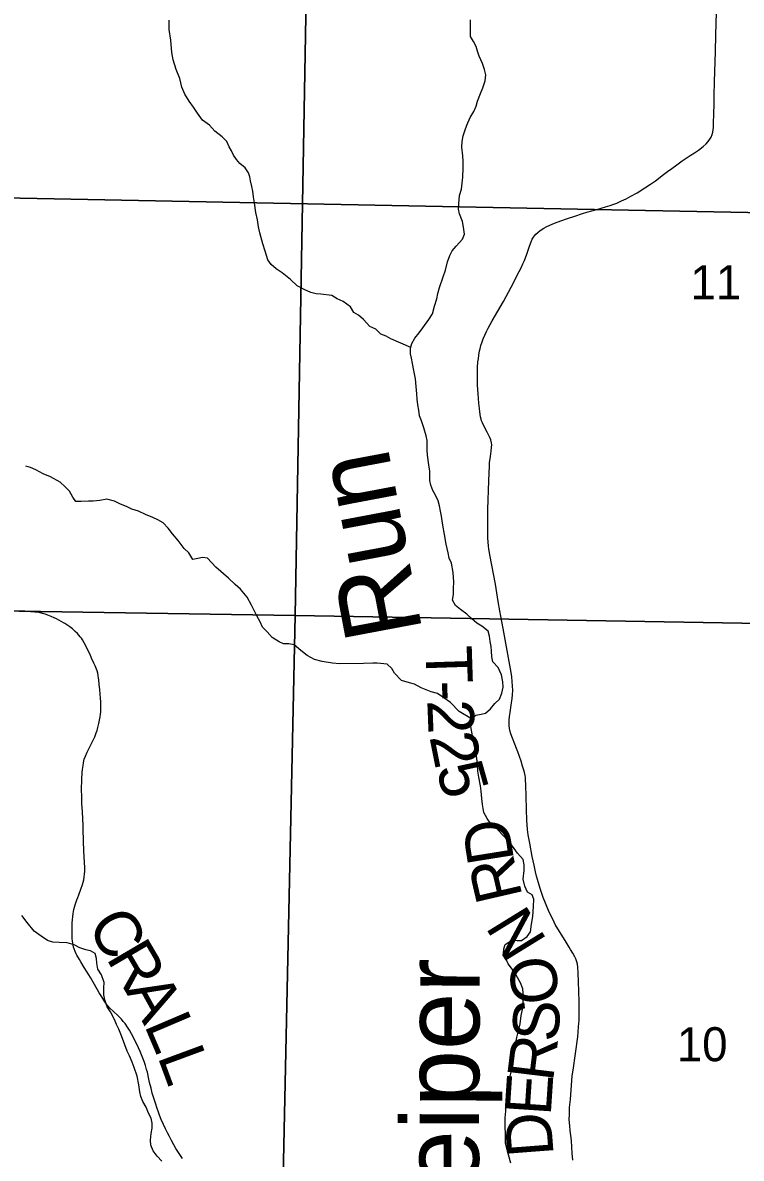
# Model space of a CAD drawing. Extents: x 0 to 34, y 0 to 22.
# Drawn here: x 21.94 to 22.822, y 17.999 to 19.394 of the extents above; entities that cross this region are included whole.
import ezdxf

# ---------------------------------------------------------------- set-up
doc = ezdxf.new("R2010")
doc.units = 0
for name, color, linetype in [('GM_X_Corporation', 7, 'Continuous'), ('GM_X_Minor_River', 7, 'Continuous'), ('GM_X_Minor_River_Text', 7, 'Continuous'), ('GM_X_Section_Text', 7, 'Continuous'), ('GM_X_Township_Road', 7, 'Continuous'), ('GM_X_Township_Road_Text', 7, 'Continuous')]:
    doc.layers.add(name, color=color, linetype=linetype)

msp = doc.modelspace()

# ---------------------------------------------------------------- linework, layer by layer
at = {"layer": 'GM_X_Corporation'}
for points in [[(25.4, 19.0068), (25.4, 20.4), (21.2921, 20.4), (21.2757, 19.6748), (21.2742, 19.6071), (21.273, 19.5535), (21.2652, 19.1913), (21.5297, 19.1865), (21.7744, 19.1817), (21.8956, 19.1793), (22.6423, 19.1645), (23.3329, 19.1508), (23.5499, 19.1465), (23.786, 19.1434), (24.169, 19.1418), (24.3186, 19.1409), (24.3186, 19.0261), (24.5766, 19.0222)], [(22.2928, 19.6778), (22.2749, 18.6656), (21.2582, 18.6819), (21.2769, 19.6922)], [(22.2928, 19.6778), (23.3052, 19.6529), (23.3004, 18.648), (22.2749, 18.6656)], [(21.2582, 18.6819), (22.2749, 18.6656), (22.2529, 17.6514), (21.2422, 17.6682)], [(22.2749, 18.6656), (23.3004, 18.648), (23.2763, 17.6399), (22.2529, 17.6514)]]:
    msp.add_lwpolyline(points, close=True, dxfattribs=at)
msp.add_lwpolyline([(25.4, 14.4307), (25.4, 19.0068), (24.5766, 19.0222), (24.3186, 19.0261), (24.3186, 19.1409), (24.169, 19.1418), (23.786, 19.1434), (23.5499, 19.1465), (23.3329, 19.1508), (22.6423, 19.1645), (21.8956, 19.1793), (21.7744, 19.1817), (21.5297, 19.1865), (21.2652, 19.1913), (20.8916, 19.1966), (20.254, 19.2058), (20.2471, 18.8539), (20.2208, 16.9558), (20.1987, 15.2691)], dxfattribs=at)
at = {"layer": 'GM_X_Minor_River'}
for points in [[(22.4167, 18.995), (22.3921, 19.0057), (22.3864, 19.0087), (22.3799, 19.0112), (22.3737, 19.0176), (22.3665, 19.0209), (22.3588, 19.0292), (22.3523, 19.0348), (22.3469, 19.0381), (22.3427, 19.0449), (22.3335, 19.0516), (22.3262, 19.0549), (22.3197, 19.059), (22.3061, 19.0603), (22.3004, 19.061), (22.2939, 19.0624), (22.2859, 19.0661), (22.2772, 19.0709), (22.2691, 19.0784), (22.2588, 19.0866), (22.2515, 19.0915), (22.2454, 19.0971), (22.2411, 19.1027), (22.2379, 19.1133), (22.2351, 19.1224), (22.2315, 19.1357), (22.2299, 19.1433), (22.2287, 19.1516), (22.2266, 19.1607), (22.2249, 19.1725), (22.2237, 19.1801), (22.2228, 19.1869), (22.2216, 19.1926), (22.22, 19.1995), (22.2192, 19.2044), (22.2176, 19.2097), (22.2133, 19.2157), (22.2068, 19.221), (22.2026, 19.2258), (22.1991, 19.2311), (22.1964, 19.2364), (22.1936, 19.2413), (22.1909, 19.2481), (22.1851, 19.2537), (22.1763, 19.2608), (22.1694, 19.268), (22.161, 19.2743), (22.1548, 19.283), (22.1498, 19.2901), (22.1447, 19.2976), (22.1393, 19.3063), (22.1358, 19.3146), (22.133, 19.3252), (22.1286, 19.3366), (22.1251, 19.3483), (22.1234, 19.3574), (22.1221, 19.3723), (22.12, 19.3856), (22.1199, 19.3913), (22.1202, 19.397)], [(22.4812, 19.2548), (22.483, 19.2613), (22.4855, 19.2682), (22.4896, 19.2774), (22.494, 19.2847), (22.497, 19.2912), (22.4984, 19.2974), (22.5024, 19.3069), (22.505, 19.3138), (22.5079, 19.3226), (22.5089, 19.3299), (22.5073, 19.3363), (22.5049, 19.3439), (22.5006, 19.353), (22.4986, 19.359), (22.497, 19.3647), (22.4935, 19.3707), (22.49, 19.3771), (22.4898, 19.3897), (22.4901, 19.3973)], [(22.4919, 18.5205), (22.4907, 18.5269), (22.4899, 18.5326), (22.4905, 18.5383), (22.4965, 18.5434), (22.5029, 18.5446), (22.5086, 18.5459), (22.5146, 18.5513), (22.5198, 18.5578), (22.5254, 18.5632), (22.5283, 18.5705), (22.5301, 18.5778), (22.5296, 18.5842), (22.528, 18.593), (22.5241, 18.602), (22.5175, 18.6088), (22.5163, 18.6149), (22.5158, 18.6221), (22.5154, 18.6278), (22.5141, 18.6339), (22.5133, 18.6403), (22.5117, 18.6464), (22.504, 18.6527), (22.4979, 18.6564), (22.4914, 18.662), (22.4856, 18.6673), (22.4776, 18.6733), (22.4715, 18.6781), (22.468, 18.6845), (22.469, 18.6918), (22.4693, 18.6994), (22.4695, 18.7066), (22.4686, 18.7188), (22.4665, 18.7302), (22.4638, 18.7362), (22.4626, 18.7427), (22.4601, 18.7533), (22.4581, 18.7654), (22.456, 18.7768), (22.4543, 18.7878), (22.4531, 18.7939), (22.4519, 18.8004), (22.4503, 18.8068), (22.4471, 18.8136), (22.4436, 18.8193), (22.4413, 18.8257), (22.4401, 18.8318), (22.44, 18.8375), (22.4399, 18.8432), (22.439, 18.8508), (22.4373, 18.8629), (22.4369, 18.869), (22.4367, 18.8808), (22.4355, 18.8865), (22.4327, 18.8963), (22.4299, 18.9051), (22.4275, 18.9111), (22.4267, 18.918), (22.4255, 18.9244), (22.4246, 18.9316), (22.4241, 18.9381), (22.4232, 18.9472), (22.4223, 18.9563), (22.4203, 18.9666), (22.419, 18.9753), (22.4174, 18.9817), (22.4162, 18.9874), (22.4165, 18.9943), (22.4179, 19), (22.4216, 19.0066), (22.4268, 19.0131), (22.4316, 19.0193), (22.4387, 19.0293), (22.4435, 19.0362), (22.446, 19.0457), (22.4485, 19.0549), (22.45, 19.0614), (22.4521, 19.0687), (22.4565, 19.0817), (22.4594, 19.0901), (22.4619, 19.1), (22.4648, 19.1081), (22.4674, 19.1138), (22.4726, 19.1196), (22.48, 19.1281), (22.4826, 19.1342), (22.4813, 19.1426), (22.4801, 19.1498), (22.4765, 19.1592), (22.4753, 19.1649), (22.4756, 19.1714), (22.4766, 19.1817), (22.4788, 19.1893), (22.4798, 19.197), (22.4804, 19.2042), (22.481, 19.2153), (22.4809, 19.2236), (22.4804, 19.2305), (22.4795, 19.2411), (22.4798, 19.248), (22.4812, 19.2548)], [(22.4913, 18.539), (22.476, 18.548), (22.4656, 18.5589), (22.4561, 18.5656), (22.4496, 18.5701), (22.4416, 18.5722), (22.4355, 18.5744), (22.4294, 18.577), (22.4214, 18.5814), (22.4153, 18.5832), (22.4054, 18.5858), (22.3966, 18.5951), (22.3935, 18.6008), (22.3877, 18.606), (22.3756, 18.6074), (22.3703, 18.6073), (22.3585, 18.6067), (22.329, 18.6063), (22.3207, 18.6073), (22.3078, 18.6094), (22.2983, 18.6119), (22.2895, 18.6167), (22.2818, 18.6227), (22.2734, 18.6298), (22.2669, 18.6308), (22.2605, 18.6311), (22.2552, 18.6333), (22.2464, 18.6389), (22.2402, 18.6456), (22.2348, 18.6516), (22.2317, 18.6581), (22.2278, 18.6652), (22.2247, 18.6713), (22.2212, 18.6785), (22.2157, 18.6883), (22.2076, 18.698), (22.2011, 18.704), (22.1931, 18.7115), (22.1773, 18.725), (22.167, 18.7362), (22.1609, 18.7369), (22.1552, 18.7357), (22.1492, 18.7344), (22.1441, 18.7427), (22.1384, 18.748), (22.131, 18.7581), (22.1241, 18.766), (22.1187, 18.7732), (22.1129, 18.7796), (22.1061, 18.7833), (22.1, 18.7862), (22.0912, 18.7899), (22.0824, 18.7939), (22.0744, 18.7965), (22.0687, 18.7994), (22.0596, 18.8031), (22.0531, 18.8064), (22.0436, 18.8086), (22.0349, 18.8069), (22.0266, 18.8064), (22.0209, 18.8063), (22.0122, 18.8058), (22.0054, 18.8057), (22.0019, 18.8113), (21.9976, 18.8185), (21.9926, 18.8238), (21.9861, 18.8297), (21.9743, 18.836), (21.9655, 18.8397), (21.9564, 18.8449), (21.9499, 18.8475), (21.9442, 18.8493)], [(22.5394, 17.993), (22.5366, 18.0032), (22.5346, 18.0112), (22.533, 18.018), (22.5325, 18.0488), (22.5332, 18.0572), (22.5338, 18.064), (22.5341, 18.0736), (22.5351, 18.0797), (22.5357, 18.0888), (22.5389, 18.1018), (22.5411, 18.1098), (22.5421, 18.1163), (22.5432, 18.1224), (22.5435, 18.1289), (22.5452, 18.1392), (22.547, 18.1476), (22.5495, 18.1575), (22.5509, 18.1644), (22.5523, 18.1743), (22.5537, 18.1819), (22.5547, 18.1907), (22.555, 18.1972), (22.5544, 18.2071), (22.5513, 18.2146), (22.5462, 18.2241), (22.5416, 18.2309), (22.5362, 18.238), (22.5334, 18.2444), (22.5307, 18.2501), (22.531, 18.2562), (22.5324, 18.2619), (22.5414, 18.2674), (22.5471, 18.2667), (22.5528, 18.2668), (22.5596, 18.2715), (22.5636, 18.2772), (22.565, 18.2868), (22.5664, 18.2959), (22.5673, 18.3085), (22.5676, 18.3173), (22.5656, 18.3229), (22.5599, 18.3259), (22.5568, 18.3335), (22.5547, 18.3418), (22.5557, 18.3525), (22.556, 18.3597), (22.5548, 18.3662), (22.5478, 18.3737), (22.5417, 18.3823), (22.5363, 18.3891), (22.5293, 18.3966), (22.5216, 18.4052), (22.5151, 18.4101), (22.5105, 18.4165), (22.5062, 18.424), (22.5049, 18.4335), (22.5041, 18.4411), (22.5032, 18.4502), (22.5023, 18.4567), (22.5003, 18.4673), (22.499, 18.4745), (22.4985, 18.4825), (22.4977, 18.4901), (22.4964, 18.4992), (22.4944, 18.5064), (22.4928, 18.5148), (22.4919, 18.5205)], [(22.1111, 17.9955), (22.1054, 18.0019), (22.1004, 18.0083), (22.0976, 18.0151), (22.0971, 18.0212), (22.0981, 18.0296), (22.0992, 18.0361), (22.0991, 18.0422), (22.0979, 18.0486), (22.0947, 18.0546), (22.092, 18.0618), (22.0877, 18.069), (22.0854, 18.0751), (22.0841, 18.0807), (22.0829, 18.0895), (22.0808, 18.1001), (22.0773, 18.1107), (22.0745, 18.1171), (22.0714, 18.1251), (22.0686, 18.1307), (22.0655, 18.1383), (22.0616, 18.1497), (22.0584, 18.1576), (22.0553, 18.1636), (22.0529, 18.1697), (22.0479, 18.1788), (22.044, 18.1852), (22.0412, 18.1939), (22.04, 18.1999), (22.0399, 18.2083), (22.0402, 18.2152), (22.037, 18.2246), (22.0327, 18.2314), (22.0311, 18.2386), (22.031, 18.2447), (22.0294, 18.2508), (22.0237, 18.2541), (22.0176, 18.2552), (22.0104, 18.2577), (22.0035, 18.2614), (21.9948, 18.2636), (21.9849, 18.2642), (21.9773, 18.2644), (21.9709, 18.2666), (21.9628, 18.2718), (21.9544, 18.2782), (21.9459, 18.2887), (21.939, 18.2973)]]:
    msp.add_lwpolyline(points, dxfattribs=at)
at = {"layer": 'GM_X_Township_Road'}
for points in [[(22.6558, 19.1676), (22.6616, 19.1694), (22.6647, 19.1705), (22.6695, 19.1724), (22.6755, 19.175), (22.6811, 19.1777), (22.687, 19.1809), (22.6945, 19.1849), (22.7042, 19.1911), (22.7108, 19.1956), (22.717, 19.1998), (22.727, 19.2073), (22.732, 19.2111), (22.7372, 19.215), (22.7431, 19.2195), (22.7498, 19.2241), (22.7595, 19.2306), (22.765, 19.2342), (22.7699, 19.2375), (22.7756, 19.2417), (22.7794, 19.2451), (22.7819, 19.2478), (22.784, 19.2508), (22.7853, 19.2532), (22.7865, 19.2564), (22.7873, 19.2595), (22.7878, 19.2623), (22.7882, 19.2652), (22.7884, 19.2693), (22.7888, 19.2833), (22.789, 19.2928), (22.7892, 19.3051), (22.7897, 19.3213), (22.7906, 19.3587), (22.791, 19.3788), (22.7922, 19.4069)], [(22.5123, 18.8877), (22.5105, 18.891), (22.5081, 18.8956), (22.5046, 18.9026), (22.5037, 18.905), (22.5031, 18.9068), (22.5024, 18.9098), (22.5014, 18.916), (22.501, 18.9199), (22.5003, 18.9265), (22.4994, 18.9382), (22.4987, 18.9487), (22.4985, 18.9562), (22.4987, 18.9705), (22.4992, 18.9774), (22.4997, 18.9812), (22.5004, 18.9856), (22.5012, 18.9909), (22.5018, 18.9935), (22.5027, 18.9973), (22.5042, 19.0019), (22.5057, 19.0058), (22.5096, 19.0148), (22.5116, 19.0188), (22.5165, 19.0276), (22.5305, 19.0515), (22.5399, 19.0692), (22.5428, 19.0745), (22.5458, 19.0806), (22.5498, 19.0883), (22.552, 19.0929), (22.5544, 19.0979), (22.5562, 19.102), (22.5592, 19.1095), (22.5604, 19.1132), (22.5622, 19.1184), (22.5636, 19.1227), (22.5645, 19.1249), (22.5659, 19.1279), (22.5672, 19.1305), (22.5684, 19.1322), (22.5702, 19.1342), (22.5726, 19.1364), (22.5757, 19.1387), (22.58, 19.1414), (22.583, 19.1431), (22.5873, 19.1452), (22.5931, 19.1476), (22.6008, 19.1505), (22.609, 19.1534), (22.6179, 19.1564), (22.6274, 19.1594), (22.6327, 19.161), (22.639, 19.1629), (22.6449, 19.1644), (22.6558, 19.1676)], [(22.6156, 17.9969), (22.6149, 18.0056), (22.6144, 18.0129), (22.6138, 18.0208), (22.6125, 18.0331), (22.6118, 18.0391), (22.6113, 18.0469), (22.6115, 18.0531), (22.6116, 18.0616), (22.6126, 18.0715), (22.615, 18.1004), (22.6159, 18.1075), (22.6216, 18.1481), (22.6222, 18.1542), (22.6227, 18.1607), (22.6232, 18.1689), (22.6235, 18.1798), (22.6236, 18.1858), (22.6235, 18.1917), (22.6231, 18.2041), (22.6227, 18.2163), (22.6222, 18.2266), (22.6217, 18.2338), (22.6213, 18.2376), (22.6207, 18.2403), (22.6193, 18.2439), (22.618, 18.2466), (22.6156, 18.2511), (22.6129, 18.2557), (22.6113, 18.2585), (22.6063, 18.2665), (22.5973, 18.281), (22.5941, 18.2864), (22.5913, 18.2921), (22.5887, 18.2974), (22.5859, 18.3036), (22.5794, 18.3196), (22.5756, 18.3304), (22.5735, 18.3373), (22.5711, 18.3455), (22.5698, 18.3508), (22.568, 18.3593), (22.5658, 18.3696), (22.5627, 18.3861), (22.5608, 18.3965), (22.5599, 18.4028), (22.5594, 18.4089), (22.5591, 18.4138), (22.5581, 18.4578), (22.5577, 18.4638), (22.5574, 18.467), (22.557, 18.4694), (22.5562, 18.473), (22.5556, 18.4757), (22.554, 18.4808), (22.5521, 18.4867), (22.5481, 18.4982), (22.5466, 18.5023), (22.5394, 18.5206), (22.5386, 18.5234), (22.5377, 18.5272), (22.5374, 18.5307), (22.5376, 18.5374), (22.538, 18.5419), (22.5386, 18.5465), (22.54, 18.5555), (22.5412, 18.564), (22.5416, 18.5685), (22.5418, 18.574), (22.5417, 18.5789), (22.5412, 18.5846), (22.5406, 18.5903), (22.5398, 18.5958), (22.5301, 18.65), (22.5285, 18.6583), (22.5261, 18.6717), (22.5241, 18.6829), (22.5205, 18.7041), (22.5138, 18.7402), (22.5133, 18.743), (22.5125, 18.7471), (22.5122, 18.7512), (22.5117, 18.7558), (22.5114, 18.7612), (22.5112, 18.7705), (22.5114, 18.7962), (22.5125, 18.8313), (22.5133, 18.8498), (22.5135, 18.8534), (22.5146, 18.8613), (22.5155, 18.8677), (22.5159, 18.8726), (22.5161, 18.8756), (22.5159, 18.8779), (22.5151, 18.8814), (22.5138, 18.8845), (22.5123, 18.8877)], [(22.0144, 18.408), (22.0136, 18.4246), (22.013, 18.4347), (22.0127, 18.4431), (22.0126, 18.4522), (22.0128, 18.4642), (22.0134, 18.4728), (22.0137, 18.4767), (22.0144, 18.4815), (22.0148, 18.4849), (22.0159, 18.4894), (22.0172, 18.493), (22.0196, 18.4981), (22.0227, 18.5044), (22.026, 18.511), (22.0287, 18.5169), (22.0305, 18.5215), (22.0316, 18.5245), (22.0327, 18.5281), (22.0337, 18.533), (22.0347, 18.5374), (22.0354, 18.5412), (22.0359, 18.5448), (22.0361, 18.5473), (22.0362, 18.5501), (22.0361, 18.5555), (22.036, 18.5602), (22.0357, 18.5637), (22.0353, 18.5695), (22.0349, 18.5747), (22.0343, 18.5816), (22.0338, 18.5866), (22.0335, 18.5888), (22.033, 18.592), (22.0323, 18.5949), (22.0315, 18.5977), (22.0291, 18.6041), (22.0277, 18.6072), (22.0249, 18.6134), (22.0229, 18.6178), (22.0204, 18.6233), (22.0178, 18.6286), (22.0137, 18.6359), (22.0123, 18.6379), (22.011, 18.6396), (22.0093, 18.6417), (22.0074, 18.6438), (22.0048, 18.6463), (22.0013, 18.6493), (21.998, 18.652), (21.997, 18.6527), (21.9918, 18.6558), (21.9876, 18.6584), (21.9816, 18.6617), (21.979, 18.663), (21.9754, 18.6646), (21.9713, 18.6662), (21.9679, 18.6673), (21.9645, 18.6683), (21.9604, 18.6693), (21.9553, 18.67), (21.9499, 18.6705), (21.9429, 18.671), (21.9351, 18.6713)], [(22.1363, 17.9988), (22.1283, 18.0112), (22.1257, 18.0157), (22.1229, 18.021), (22.1203, 18.0259), (22.118, 18.0305), (22.1155, 18.0355), (22.1133, 18.0406), (22.1103, 18.0469), (22.1083, 18.052), (22.1069, 18.0559), (22.1054, 18.0601), (22.1032, 18.0668), (22.1012, 18.0731), (22.0994, 18.0792), (22.0978, 18.0854), (22.0961, 18.0922), (22.0952, 18.0965), (22.0933, 18.1048), (22.0924, 18.1082), (22.0909, 18.1132), (22.0892, 18.1181), (22.0879, 18.1219), (22.0845, 18.1304), (22.0825, 18.1349), (22.0759, 18.1484), (22.0739, 18.152), (22.0713, 18.1566), (22.0689, 18.1603), (22.066, 18.1645), (22.0638, 18.1673), (22.0614, 18.1702), (22.0569, 18.1745), (22.0518, 18.1793), (22.0472, 18.1837), (22.0451, 18.186), (22.042, 18.1898), (22.041, 18.1913), (22.0373, 18.1974), (22.0342, 18.2025), (22.0284, 18.2124), (22.0233, 18.2211), (22.0193, 18.2277), (22.0158, 18.2335), (22.0115, 18.2404), (22.0098, 18.2434), (22.0068, 18.2485), (22.0061, 18.2501), (22.0047, 18.2532), (22.0035, 18.2563), (22.0028, 18.2586), (22.0022, 18.2614), (22.0015, 18.2657), (22.0011, 18.2689), (22.0009, 18.2719), (22.001, 18.2885), (22.0012, 18.2922), (22.0017, 18.2963), (22.0022, 18.2999), (22.0032, 18.3046), (22.0048, 18.3104), (22.0059, 18.3141), (22.0068, 18.3167), (22.0079, 18.3195), (22.0091, 18.3227), (22.0118, 18.3298), (22.0137, 18.3353), (22.0145, 18.3382), (22.0152, 18.3413), (22.0157, 18.3447), (22.0161, 18.348), (22.0164, 18.3519), (22.0165, 18.3554), (22.0161, 18.3631), (22.0159, 18.3687), (22.015, 18.3874), (22.0145, 18.4049), (22.0144, 18.408)]]:
    msp.add_lwpolyline(points, dxfattribs=at)

# ---------------------------------------------------------------- texts
at = {"layer": 'GM_X_Minor_River_Text'}
for s, rotation, p in [('Run', 100.694, (22.4313, 18.6461)), ('Leiper', 89.7662, (22.4998, 17.8926))]:
    msp.add_text(s, height=0.09468, rotation=rotation, dxfattribs=at).set_placement(p)
at = {"layer": 'GM_X_Section_Text'}
for s, p in [('11', (22.76, 19.0542)), ('10', (22.7433, 18.1183))]:
    msp.add_text(s, height=0.04186, rotation=0, dxfattribs=at).set_placement(p)
at = {"layer": 'GM_X_Township_Road_Text'}
for s, rotation, p in [('T', 271.8646, (22.4347, 18.6278)), ('-', 271.9299, (22.4361, 18.5852)), ('2', 272.2365, (22.4369, 18.5616)), ('2', 281.3127, (22.4394, 18.5169)), ('5', 285.6701, (22.4474, 18.478)), ('D', 99.1126, (22.5437, 18.3652)), ('R', 103.0546, (22.5541, 18.3208)), ('C', 300.4289, (22.0184, 18.2854)), ('N', 121.6985, (22.5847, 18.2664)), ('R', 300.4115, (22.042, 18.2452)), ('O', 97.1103, (22.5997, 18.1919)), ('A', 298.9555, (22.0655, 18.2053)), ('S', 85.6259, (22.5971, 18.1412)), ('L', 293.0669, (22.089, 18.1629)), ('R', 83.0749, (22.5912, 18.0922)), ('L', 290.2716, (22.1054, 18.1245)), ('E', 86.1788, (22.5884, 18.0506)), ('D', 94.3811, (22.5922, 18.0029))]:
    msp.add_text(s, height=0.0568, rotation=rotation, dxfattribs=at).set_placement(p)

doc.saveas('drawing.dxf')
